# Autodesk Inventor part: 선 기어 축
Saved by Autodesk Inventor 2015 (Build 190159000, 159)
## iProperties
Created: 2026-05
Part Number: 선 기어 축
Material: 일반
Document SubType Name: Modeling
Designer: 104
Density: 1 g/cm^3
Appearance: 기본값
Author: 104
Author: jhkim
Creation Date: 2026-04-27
Sending System: Autodesk Inventor 2027
Preprocessor: ST-DEVELOPER v20.1
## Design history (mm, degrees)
node "선 기어 축1"
node "솔리드1"
node "기준1"
